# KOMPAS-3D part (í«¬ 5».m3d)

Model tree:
1. Эскиз:1
2. Операция выдавливания:1
     Расстояние 1 = 2
3. Эскиз:2
4. Операция выдавливания:2
     Расстояние 1 = 5
5. Эскиз:3
6. Операция выдавливания:3
     Расстояние 1 = 2
7. Эскиз:4
8. Операция выдавливания:4
     Расстояние 1 = 60
9. Эскиз:5
10. Операция выдавливания:5
     Расстояние 1 = 2
11. Эскиз:6
12. Операция выдавливания:6
     Расстояние 1 = 4.5
13. Эскиз:7
14. Операция выдавливания:7
     Расстояние 1 = 2
15. Скругление:1
     Радиус = 1
16. Скругление:2
     Радиус = 1
17. Эскиз:8
18. Вырезать элемент выдавливания:1
     Расстояние 1 = 10; Угол 1 = 35
19. Эскиз:9
20. Вырезать элемент выдавливания:2
     Расстояние 1 = 10; Угол 1 = 35
21. Эскиз:10
22. Вырезать элемент выдавливания:3
     Расстояние 2 = 22; Расстояние 1 = 22; Угол 1 = 35
23. Эскиз:11
24. Вырезать элемент выдавливания:4
     Расстояние 2 = 2; Расстояние 1 = 2
25. Эскиз:12
26. Вырезать элемент выдавливания:5
     Расстояние 2 = 2; Расстояние 1 = 2; Угол 1 = 35
27. Эскиз:13
28. Вырезать элемент выдавливания:6
     Расстояние 2 = 2; Расстояние 1 = 122
29. Эскиз:15
30. Операция выдавливания:9
     Расстояние 1 = 10; Расстояние 2 = 0.5
